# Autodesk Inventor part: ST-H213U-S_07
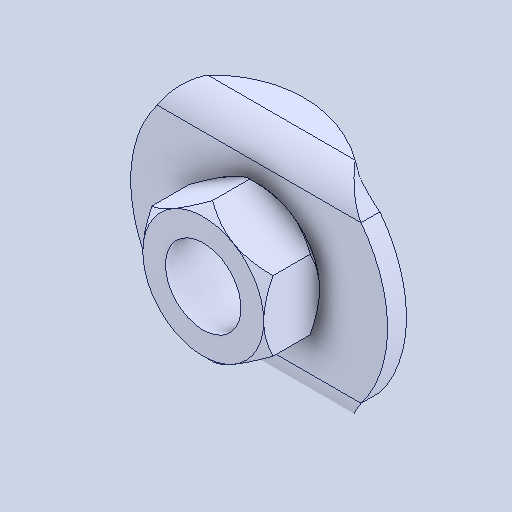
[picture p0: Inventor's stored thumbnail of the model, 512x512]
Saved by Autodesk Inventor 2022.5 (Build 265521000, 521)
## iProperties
Created: 2024-07
Part Number: ST-H213U-S_07
Material: 一般
Document SubType Name: Modeling
Designer: ImaoCorp
Density: 1 g/cm^3
Appearance: 既定
Author: ImaoCorp
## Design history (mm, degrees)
feature "ST-H213U-S_07"
node "ソリッド1"
